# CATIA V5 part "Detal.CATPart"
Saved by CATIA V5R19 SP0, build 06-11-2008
Bounding box of the stored display mesh (mm): x -33.45 to 92.119, y -44.001 to 49.85, z 0 to 20
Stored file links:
  G:\Catia\CD\Narzedzia\Modele brylowe narzedzi\Detal.CATPart
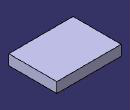
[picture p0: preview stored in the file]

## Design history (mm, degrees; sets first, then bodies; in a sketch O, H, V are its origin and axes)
Body1 (main body)
  Sketch1 on xy-plane, origin (0, 0, 0), H (1, 0, 0), V (0, 1, 0)
    line L1 (-33.4497, 49.8502) -> (92.1195, 49.8502)
    line L2 (92.1195, 49.8502) -> (92.1195, -44.0011)
    line L3 (92.1195, -44.0011) -> (-33.4497, -44.0011)
    line L4 (-33.4497, -44.0011) -> (-33.4497, 49.8502)
    length L1 = 125.5692
    horizontal: L1 H, L3 H
    vertical: L2 V, L4 V
  Pad1: profile Sketch1, direction (0, 0, 1), length 20
Body2
  Sketch2 on start face of Pad1, origin (0, 0, 0), H (1, 0, 0), V (0, -1, 0)
    line L1 (-34.1807, 43.542) -> (92.6585, 43.542)
    line L2 (92.6585, 43.542) -> (92.6585, -49.8675)
    line L3 (92.6585, -49.8675) -> (-34.1807, -49.8675)
    line L4 (-34.1807, -49.8675) -> (-34.1807, 43.542)
    horizontal: L1 H, L3 H
    vertical: L2 V, L4 V
  Pad2: profile Sketch2, direction (0, 0, 1), length 23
